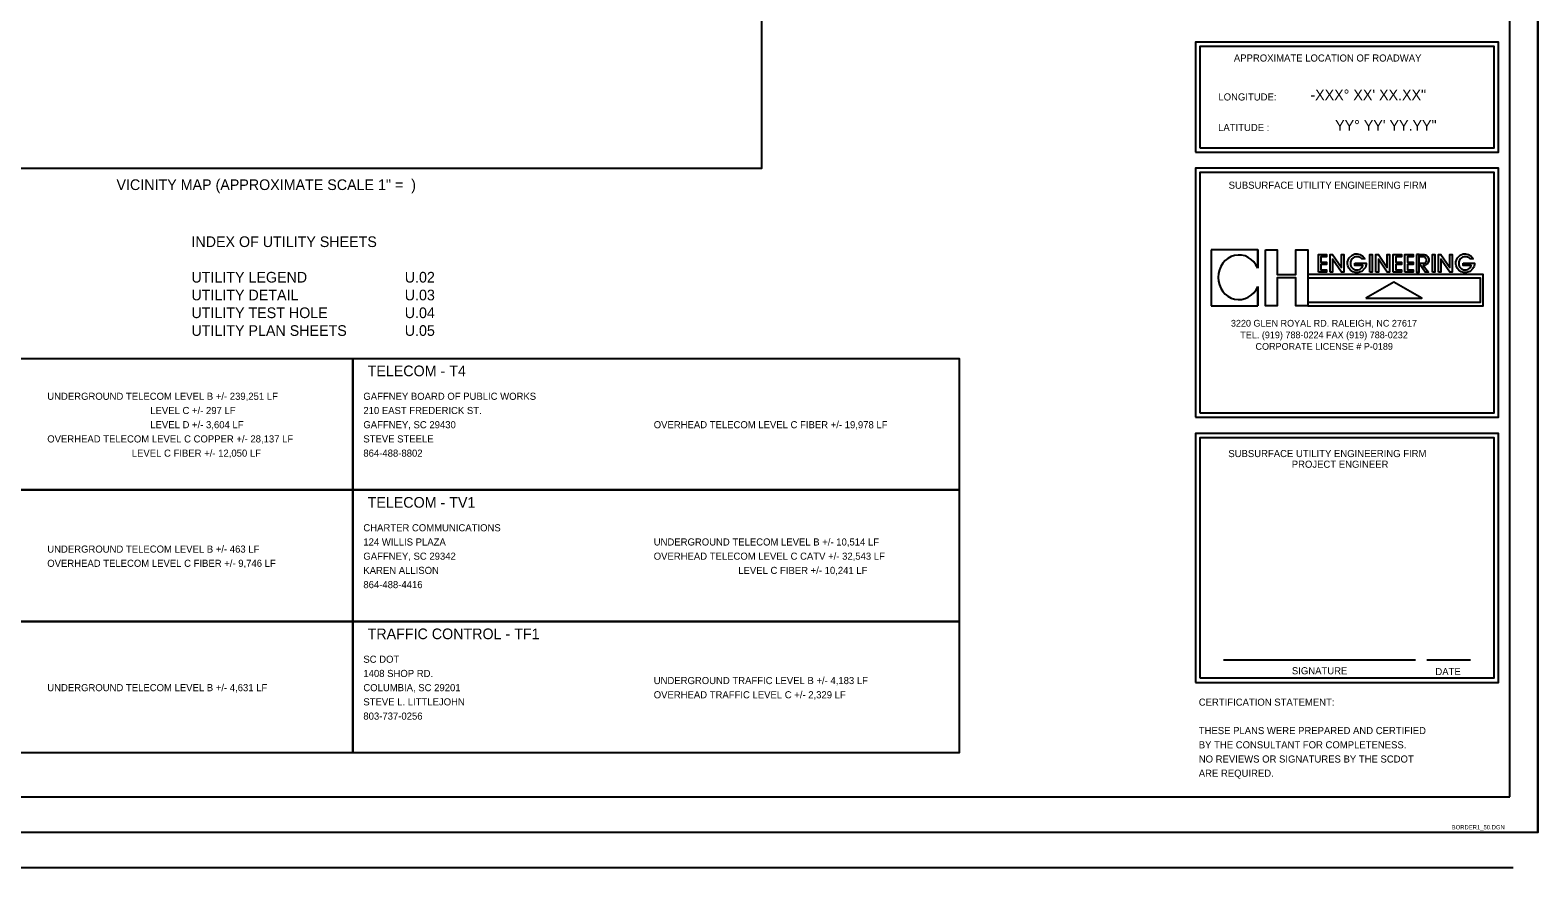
# Model space of a CAD drawing. Extents: x 189971 to 191767, y 195697 to 196847.
# Drawn here: x 190707 to 191767, y 195697 to 196286 of the extents above; entities that cross this region are included whole.
import ezdxf

# ---------------------------------------------------------------- set-up
doc = ezdxf.new("R2010")
doc.units = 0
for name, color, linetype in [('Default', 7, 'Continuous'), ('RD_SHT_Bndy', 7, 'Continuous'), ('RD_SHT_Iplotshp', 7, 'Continuous'), ('RD_SHT_Snap', 7, 'Continuous'), ('RD_SHT_TX', 7, 'Continuous')]:
    doc.layers.add(name, color=color, linetype=linetype)

msp = doc.modelspace()

# ---------------------------------------------------------------- linework, layer by layer
at = {"layer": 'Default'}
for p, q in [((191570.4, 196132), (191570.4, 196119)), ((191683.8, 196128.7), (191682.1, 196128.7)), ((191570.4, 196106.2), (191570.4, 196092.5)), ((191537.6, 196092.5), (191570.4, 196092.5))]:
    msp.add_line(p, q, dxfattribs=at)
for points in [[(191537.6, 196132), (191537.6, 196092.5)], [(191570.4, 196119), (191570.4, 196132), (191537.6, 196132)], [(191613.1, 196116.2), (191613.1, 196128.7), (191618.8, 196128.7), (191618.8, 196127), (191614.8, 196127), (191614.8, 196123.3), (191618.8, 196123.3), (191618.8, 196121.6), (191614.8, 196121.6), (191614.8, 196117.9), (191618.8, 196117.9), (191618.8, 196116.2), (191613.1, 196116.2)], [(191621.3, 196116.2), (191621.3, 196128.7), (191623, 196128.7), (191629.3, 196119.6), (191629.3, 196128.7), (191631, 196128.7), (191631, 196116.2), (191629.3, 196116.2), (191623, 196125.3), (191623, 196116.2), (191621.3, 196116.2)], [(191638.7, 196122.5), (191646.6, 196122.5), (191646.6, 196121.6), (191646.3, 196120.5), (191646.1, 196119.6), (191645.5, 196118.8), (191643.5, 196116.8), (191640.9, 196115.9), (191638.9, 196115.9), (191637.2, 196116.5), (191635.5, 196117.6), (191634.4, 196119.1), (191633.8, 196120.8), (191633.5, 196121.9), (191633.5, 196123.6), (191634.1, 196125.3), (191634.7, 196126.2), (191636.7, 196128.2), (191638.7, 196129), (191640.4, 196129), (191642.4, 196128.7), (191644.1, 196127.6), (191645.2, 196126.4), (191645.8, 196125.6), (191643.5, 196125.6), (191642.9, 196126.2), (191641.2, 196127), (191639.2, 196127), (191638.1, 196126.7), (191637.5, 196126.4), (191636.4, 196125.3), (191635.5, 196123.6), (191635.5, 196121.6), (191635.8, 196120.5), (191636.1, 196119.9), (191637.2, 196118.8), (191638.9, 196117.9), (191640.9, 196117.9), (191642.1, 196118.2), (191642.6, 196118.5), (191643.8, 196119.6), (191644.3, 196120.8), (191638.7, 196120.8), (191638.7, 196122.5)], [(191649.2, 196116.2), (191649.2, 196128.7), (191650.9, 196128.7), (191650.9, 196116.2), (191649.2, 196116.2)], [(191653.4, 196116.2), (191653.4, 196128.7), (191655.2, 196128.7), (191661.4, 196119.6), (191661.4, 196128.7), (191663.1, 196128.7), (191663.1, 196116.2), (191661.4, 196116.2), (191655.2, 196125.3), (191655.2, 196116.2), (191653.4, 196116.2)], [(191665.7, 196116.2), (191665.7, 196128.7), (191671.4, 196128.7), (191671.4, 196127), (191667.4, 196127), (191667.4, 196123.3), (191671.4, 196123.3), (191671.4, 196121.6), (191667.4, 196121.6), (191667.4, 196117.9), (191671.4, 196117.9), (191671.4, 196116.2), (191665.7, 196116.2)], [(191671.4, 196123), (191671.4, 196121.9)], [(191673.9, 196116.2), (191673.9, 196128.7), (191679.6, 196128.7), (191679.6, 196127), (191675.6, 196127), (191675.6, 196123.3), (191679.6, 196123.3), (191679.6, 196121.6), (191675.6, 196121.6), (191675.6, 196117.9), (191679.6, 196117.9), (191679.6, 196116.2), (191673.9, 196116.2)], [(191679.6, 196123), (191679.6, 196121.9)], [(191682.1, 196128.7), (191682.1, 196116.2), (191683.8, 196116.2), (191683.8, 196128.7)], [(191690.7, 196125.6), (191690.7, 196123.9)], [(191693.2, 196116.2), (191693.2, 196128.7), (191694.9, 196128.7), (191694.9, 196116.2), (191693.2, 196116.2)], [(191697.5, 196116.2), (191697.5, 196128.7), (191699.2, 196128.7), (191705.5, 196119.6), (191705.5, 196128.7), (191707.2, 196128.7), (191707.2, 196116.2), (191705.5, 196116.2), (191699.2, 196125.3), (191699.2, 196116.2), (191697.5, 196116.2)], [(191714.8, 196122.5), (191722.8, 196122.5), (191722.8, 196121.6), (191722.5, 196120.5), (191722.2, 196119.6), (191721.7, 196118.8), (191719.7, 196116.8), (191717.1, 196115.9), (191715.1, 196115.9), (191713.4, 196116.5), (191711.7, 196117.6), (191710.6, 196119.1), (191710, 196120.8), (191709.7, 196121.9), (191709.7, 196123.6), (191710.3, 196125.3), (191710.9, 196126.2), (191712.8, 196128.2), (191714.8, 196129), (191716.5, 196129), (191718.5, 196128.7), (191720.2, 196127.6), (191721.4, 196126.4), (191721.9, 196125.6), (191719.7, 196125.6), (191719.1, 196126.2), (191717.4, 196127), (191715.4, 196127), (191714.3, 196126.7), (191713.7, 196126.4), (191712.6, 196125.3), (191711.7, 196123.6), (191711.7, 196121.6), (191712, 196120.5), (191712.3, 196119.9), (191713.4, 196118.8), (191715.1, 196117.9), (191717.1, 196117.9), (191718.2, 196118.2), (191718.8, 196118.5), (191720, 196119.6), (191720.5, 196120.8), (191714.8, 196120.8), (191714.8, 196122.5)], [(191605.5, 196114.6), (191605.5, 196112.3)], [(191605.5, 196092.5), (191729, 196092.5), (191729, 196114.6), (191605.5, 196114.6)], [(191605.5, 196112.3), (191726.7, 196112.3), (191726.7, 196094.8), (191605.5, 196094.8)], [(191671.4, 196117.6), (191671.4, 196116.5)], [(191679.6, 196117.6), (191679.6, 196116.5)], [(191570.4, 196092.5), (191570.4, 196106.2)], [(191605.5, 196094.8), (191605.5, 196092.5)]]:
    msp.add_lwpolyline(points, dxfattribs=at)
for points in [[(191575.8, 196132), (191584.1, 196132), (191584.1, 196114.6), (191597.1, 196114.6), (191597.1, 196132), (191605.5, 196132), (191605.5, 196092.5), (191597.1, 196092.5), (191597.1, 196112.3), (191584.1, 196112.3), (191584.1, 196092.5), (191575.8, 196092.5)], [(191683.8, 196128.7), (191687.3, 196128.7), (191688.4, 196128.4), (191689, 196128.2), (191689.8, 196127.3), (191690.7, 196125.6), (191690.7, 196123.9), (191690.1, 196122.8), (191689.5, 196121.9), (191688.7, 196121.3), (191688.1, 196121), (191686.7, 196121), (191690.4, 196116.2), (191688.1, 196116.2), (191683.8, 196122.2), (191683.8, 196122.5), (191687.3, 196122.5), (191688.1, 196122.8), (191688.7, 196123.6), (191689, 196124.2), (191689, 196125.3), (191688.7, 196125.9), (191688.1, 196126.7), (191687.3, 196127), (191683.8, 196127)], [(191646.5, 196097.9), (191685.7, 196097.9), (191666.1, 196109.2)]]:
    msp.add_lwpolyline(points, close=True, dxfattribs=at)
msp.add_ellipse((191557.1, 196112.6), major_axis=(-0.2, -15.7), ratio=0.926238, start_param=2.005764, end_param=7.447996, dxfattribs=at)
at = {"layer": 'RD_SHT_Bndy'}
for p, q in [((191747.6, 195747.1), (191747.6, 196797.1)), ((190072.6, 195747.1), (191747.6, 195747.1)), ((191750, 195722.1), (189990, 195722.1)), ((191750, 195697.1), (189990, 195697.1))]:
    msp.add_line(p, q, dxfattribs=at)
for points in [[(190596.7, 196189.3), (191221.7, 196189.3), (191221.7, 196564.3), (190596.7, 196564.3)], [(191526.6, 196200.6), (191739.7, 196200.6), (191739.7, 196278), (191526.6, 196278)], [(191529.7, 196203.7), (191736.6, 196203.7), (191736.6, 196275), (191529.7, 196275)], [(191526.6, 196014.1), (191739.7, 196014.1), (191739.7, 196189.4), (191526.6, 196189.4)], [(191529.7, 196017.2), (191736.6, 196017.2), (191736.6, 196186.3), (191529.7, 196186.3)], [(190507.4, 196055.5), (190933.9, 196055.5), (190933.9, 195963), (190507.4, 195963)], [(190933.9, 196055.5), (191360.3, 196055.5), (191360.3, 195963), (190933.9, 195963)], [(191526.6, 195827.6), (191739.7, 195827.6), (191739.7, 196002.8), (191526.6, 196002.8)], [(191529.7, 195830.7), (191736.6, 195830.7), (191736.6, 195999.7), (191529.7, 195999.7)], [(190507.4, 195963), (190933.9, 195963), (190933.9, 195870.5), (190507.4, 195870.5)], [(190933.9, 195963), (191360.3, 195963), (191360.3, 195870.5), (190933.9, 195870.5)], [(190507.4, 195870.5), (190933.9, 195870.5), (190933.9, 195778), (190507.4, 195778)], [(190933.9, 195870.5), (191360.3, 195870.5), (191360.3, 195778), (190933.9, 195778)]]:
    msp.add_lwpolyline(points, close=True, dxfattribs=at)
at = {"layer": 'RD_SHT_Iplotshp'}
msp.add_lwpolyline([(189971.4, 196822.1), (191767.4, 196822.1), (191767.4, 195722.1), (189971.4, 195722.1)], close=True, dxfattribs=at)
at = {"layer": 'RD_SHT_Snap'}
msp.add_line((191767.4, 195722.1), (191767.4, 196822.1), dxfattribs=at)
at = {"layer": 'RD_SHT_TX'}
for p, q in [((191546.3, 195843.5), (191681.3, 195843.5)), ((191689.4, 195843.5), (191720, 195843.5))]:
    msp.add_line(p, q, dxfattribs=at)

# ---------------------------------------------------------------- texts
at = {"layer": 'Default'}
for s, p in [('3220 GLEN ROYAL RD. RALEIGH, NC 27617', (191551.5, 196077.9)), ('TEL. (919) 788-0224 FAX (919) 788-0232', (191558.1, 196069.7)), ('CORPORATE LICENSE # P-0189', (191568.8, 196061.6))]:
    msp.add_text(s, height=4.746, rotation=0.0001, dxfattribs=at).set_placement(p)
at = {"layer": 'RD_SHT_TX'}
for s, height, p in [('APPROXIMATE LOCATION OF ROADWAY', 5, (191553.6, 196264.4)), ('LONGITUDE: ', 5, (191542.7, 196237)), ('-XXX%%d XX\' XX.XX"', 7.5, (191607.4, 196237.2)), ('LATITUDE : ', 5, (191542.5, 196215.5)), ('YY%%d YY\' YY.YY"', 7.5, (191624.8, 196215.7)), ('VICINITY MAP (APPROXIMATE SCALE 1" =  )', 7.5, (190767.8, 196174)), ('SUBSURFACE UTILITY ENGINEERING FIRM', 5, (191549.9, 196174.9)), ('INDEX OF UTILITY SHEETS', 7.5, (190820.5, 196133.9)), ('UTILITY LEGEND ', 7.5, (190820.5, 196108.9)), ('U.02', 7.5, (190970.5, 196108.9)), ('UTILITY DETAIL', 7.5, (190820.5, 196096.4)), ('U.03', 7.5, (190970.5, 196096.4)), ('UTILITY TEST HOLE', 7.5, (190820.5, 196083.9)), ('U.04', 7.5, (190970.5, 196083.9)), ('UTILITY PLAN SHEETS', 7.5, (190820.5, 196071.4)), ('U.05', 7.5, (190970.5, 196071.4)), ('TELECOM - T4', 7.5, (190944.4, 196043)), ('UNDERGROUND TELECOM LEVEL B +/- 239,251 LF', 5, (190719.1, 196026.4)), ('GAFFNEY BOARD OF PUBLIC WORKS', 5, (190941.4, 196026.4)), ('                                       LEVEL C +/- 297 LF', 5, (190719.1, 196016.4)), ('210 EAST FREDERICK ST.', 5, (190941.4, 196016.4)), ('                                       LEVEL D +/- 3,604 LF', 5, (190719.1, 196006.4)), ('GAFFNEY, SC 29430', 5, (190941.4, 196006.4)), ('OVERHEAD TELECOM LEVEL C FIBER +/- 19,978 LF', 5, (191145.6, 196006.4)), ('OVERHEAD TELECOM LEVEL C COPPER +/- 28,137 LF', 5, (190719.1, 195996.4)), ('STEVE STEELE', 5, (190941.4, 195996.4)), ('                                LEVEL C FIBER +/- 12,050 LF', 5, (190719.1, 195986.4)), ('864-488-8802', 5, (190941.4, 195986.4)), ('SUBSURFACE UTILITY ENGINEERING FIRM', 5, (191549.7, 195986.1)), ('PROJECT ENGINEER', 5, (191594.3, 195978.6)), ('TELECOM - TV1', 7.5, (190944.4, 195950.5)), ('CHARTER COMMUNICATIONS', 5, (190941.4, 195933.9)), ('UNDERGROUND TELECOM LEVEL B +/- 463 LF', 5, (190719.1, 195918.9)), ('GAFFNEY, SC 29342', 5, (190941.4, 195913.9)), ('124 WILLIS PLAZA', 5, (190941.4, 195923.9)), ('OVERHEAD TELECOM LEVEL C CATV +/- 32,543 LF', 5, (191145.6, 195913.9)), ('UNDERGROUND TELECOM LEVEL B +/- 10,514 LF', 5, (191145.6, 195923.9)), ('OVERHEAD TELECOM LEVEL C FIBER +/- 9,746 LF', 5, (190719.1, 195908.9)), ('KAREN ALLISON', 5, (190941.4, 195903.9)), ('                                LEVEL C FIBER +/- 10,241 LF', 5, (191145.6, 195903.9)), ('864-488-4416', 5, (190941.4, 195893.9)), ('TRAFFIC CONTROL - TF1', 7.5, (190944.4, 195858)), ('SC DOT', 5, (190941.4, 195841.4)), ('1408 SHOP RD.', 5, (190941.4, 195831.4)), ('SIGNATURE', 5, (191594.4, 195833.3)), ('DATE', 5, (191695.3, 195832.7)), ('UNDERGROUND TELECOM LEVEL B +/- 4,631 LF', 5, (190719.1, 195821.4)), ('COLUMBIA, SC 29201', 5, (190941.4, 195821.4)), ('UNDERGROUND TRAFFIC LEVEL B +/- 4,183 LF', 5, (191145.6, 195826.4)), ('STEVE L. LITTLEJOHN', 5, (190941.4, 195811.4)), ('OVERHEAD TRAFFIC LEVEL C +/- 2,329 LF', 5, (191145.6, 195816.4)), ('CERTIFICATION STATEMENT:', 5, (191528.9, 195811.2)), ('803-737-0256', 5, (190941.4, 195801.4)), ('THESE PLANS WERE PREPARED AND CERTIFIED', 5, (191528.9, 195791.2)), ('BY THE CONSULTANT FOR COMPLETENESS.', 5, (191528.9, 195781.2)), ('NO REVIEWS OR SIGNATURES BY THE SCDOT', 5, (191528.9, 195771.2)), ('ARE REQUIRED.', 5, (191528.9, 195761.2)), ('BORDER1_50.DGN', 3, (191706.8, 195724.2))]:
    msp.add_text(s, height=height, dxfattribs=at).set_placement(p)

doc.saveas('drawing.dxf')
